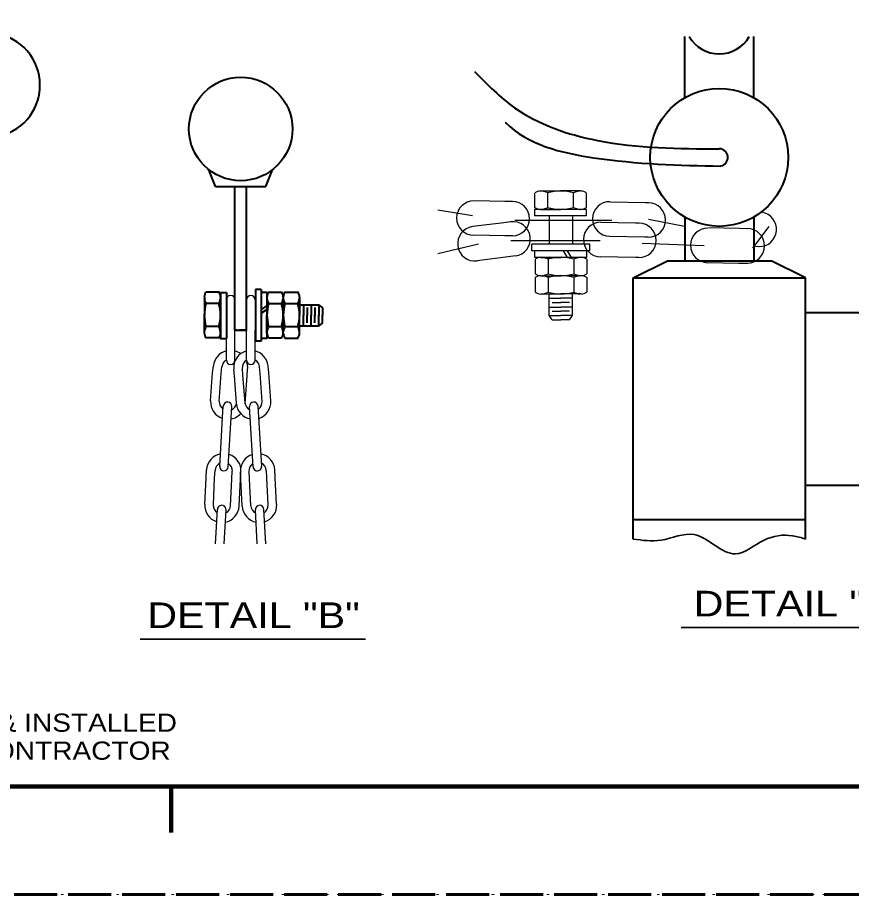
# Model space of a CAD drawing. Extents: x 312583 to 312854, y 144419 to 144597.
# Drawn here: x 312726.34 to 312761.09, y 144418.58 to 144455.15 of the extents above; entities that cross this region are included whole.
import ezdxf
from ezdxf.enums import TextEntityAlignment as Align

# ---------------------------------------------------------------- set-up
doc = ezdxf.new("R2010")
doc.units = 0
doc.header["$LTSCALE"] = 0.3
doc.linetypes.add('DOTTED', pattern=[1.5, 0.3, -1.2])
doc.linetypes.add('LONG_DASHED', pattern=[7.5, 6, -1.5])
for name, color, linetype, lineweight in [('1', 7, 'Continuous', 40), ('62', 7, 'DOTTED', 13), ('63', 7, 'LONG_DASHED', 60)]:
    doc.layers.add(name, color=color, linetype=linetype, lineweight=lineweight)

msp = doc.modelspace()

# ---------------------------------------------------------------- linework, layer by layer
at = {"layer": '1'}
for p, q in [((312754.1462, 144451.8031), (312754.1462, 144454.3561)), ((312757.0212, 144451.8031), (312757.0212, 144454.3561)), ((312734.588, 144448.104), (312734.3197, 144448.8017)), ((312736.6964, 144448.104), (312736.9724, 144448.8017)), ((312734.588, 144448.104), (312736.6964, 144448.104)), ((312735.4007, 144442.1164), (312735.4007, 144448.104)), ((312754.1462, 144446.8274), (312754.1462, 144445.0104)), ((312757.0212, 144446.8274), (312757.0212, 144445.0104)), ((312759.1832, 144444.2898), (312757.7419, 144445.0104)), ((312735.8837, 144442.1164), (312735.8837, 144444.2477)), ((312751.9919, 144444.2898), (312759.1832, 144444.2898)), ((312751.9919, 144434.2234), (312751.9919, 144444.2898)), ((312759.1832, 144434.2234), (312759.1832, 144444.2898)), ((312734.7414, 144443.7034), (312734.197, 144443.7034)), ((312734.8027, 144443.688), (312735.048, 144443.688)), ((312735.048, 144443.688), (312735.048, 144441.7714)), ((312736.497, 144443.8107), (312736.2594, 144443.8107)), ((312736.2594, 144443.8107), (312736.2594, 144441.6564)), ((312736.497, 144443.8107), (312736.497, 144441.6564)), ((312736.7347, 144443.688), (312736.497, 144443.688)), ((312736.7347, 144443.688), (312736.7347, 144441.7714)), ((312736.796, 144443.7034), (312737.348, 144443.7034)), ((312737.4784, 144443.6957), (312738.0304, 144443.6957)), ((312734.128, 144443.4887), (312734.128, 144442.7297)), ((312734.8027, 144443.4887), (312734.8027, 144442.7297)), ((312736.7347, 144443.4887), (312736.7347, 144442.7297)), ((312737.417, 144443.4887), (312737.417, 144442.7297)), ((312737.417, 144443.4887), (312737.417, 144442.7297)), ((312738.0994, 144443.4887), (312738.0994, 144442.7297)), ((312734.7414, 144443.2204), (312734.1894, 144443.2204)), ((312736.497, 144442.9674), (312736.7347, 144443.1207)), ((312736.497, 144442.8217), (312736.7347, 144442.975)), ((312736.8037, 144443.2204), (312737.348, 144443.2204)), ((312737.4784, 144443.2204), (312738.0304, 144443.2204)), ((312738.0994, 144443.1667), (312738.8967, 144443.1667)), ((312738.2527, 144443.1667), (312738.2527, 144442.7297)), ((312738.4137, 144443.0517), (312738.4137, 144442.7297)), ((312738.5747, 144443.1667), (312738.5747, 144442.7297)), ((312738.7357, 144443.0517), (312738.7357, 144442.7297)), ((312739.0577, 144443.0517), (312739.0577, 144442.7297)), ((312734.128, 144441.9937), (312734.128, 144442.7374)), ((312734.8027, 144441.9937), (312734.8027, 144442.7297)), ((312736.7347, 144441.9937), (312736.7347, 144442.7297)), ((312737.417, 144441.9937), (312737.417, 144442.7374)), ((312737.417, 144441.9937), (312737.417, 144442.7297)), ((312738.0994, 144441.9937), (312738.0994, 144442.7374)), ((312738.2527, 144442.3004), (312738.2527, 144442.7374)), ((312738.4137, 144442.4154), (312738.4137, 144442.7374)), ((312738.5747, 144442.3004), (312738.5747, 144442.7374)), ((312738.7357, 144442.4154), (312738.7357, 144442.7374)), ((312739.0577, 144442.4154), (312739.0577, 144442.7374)), ((312734.7414, 144442.2697), (312734.197, 144442.2697)), ((312736.796, 144442.2697), (312737.348, 144442.2697)), ((312737.4784, 144442.2697), (312738.0304, 144442.2697)), ((312738.0994, 144442.3004), (312738.8967, 144442.3004)), ((312735.8837, 144442.1164), (312735.5847, 144442.1164)), ((312734.7414, 144441.7867), (312734.197, 144441.7867)), ((312736.497, 144441.6564), (312736.2594, 144441.6564)), ((312736.7347, 144441.7714), (312736.497, 144441.7714)), ((312736.796, 144441.7867), (312737.348, 144441.7867)), ((312737.4784, 144441.779), (312738.0304, 144441.779)), ((312759.1832, 144435.6571), (312762.0582, 144435.6571)), ((312751.9919, 144434.2234), (312759.1832, 144434.2234)), ((312751.9919, 144433.4031), (312751.9919, 144434.2234)), ((312759.1832, 144433.4031), (312759.1832, 144434.2234))]:
    msp.add_line(p, q, dxfattribs=at)
at = {"layer": '1', "lineweight": 25}
for p, q in [((312747.8979, 144447.2184), (312747.8979, 144447.8318)), ((312748.1355, 144447.9161), (312748.9712, 144447.9161)), ((312748.4422, 144447.2184), (312748.4422, 144447.8318)), ((312749.8145, 144447.9161), (312748.9635, 144447.9161)), ((312749.5155, 144447.2184), (312749.5155, 144447.8394)), ((312750.0522, 144447.2184), (312750.0522, 144447.8318)), ((312743.8575, 144447.1341), (312745.2989, 144446.8964)), ((312748.1355, 144447.1494), (312748.9635, 144447.1494)), ((312749.8222, 144447.1494), (312748.9635, 144447.1494)), ((312750.0445, 144447.1494), (312750.0445, 144446.8811)), ((312747.0622, 144446.6971), (312751.1102, 144446.6971)), ((312750.0445, 144446.8811), (312747.8902, 144446.8811)), ((312749.6842, 144446.8811), (312748.2735, 144446.8811)), ((312748.4959, 144446.8811), (312748.4959, 144445.6928)), ((312749.4695, 144446.8811), (312749.4695, 144445.6928)), ((312752.6359, 144446.7431), (312754.1309, 144446.4518)), ((312756.9829, 144445.5318), (312757.6575, 144446.4364)), ((312746.9012, 144445.8461), (312750.6272, 144445.8461)), ((312745.5519, 144445.7004), (312743.8575, 144445.3018)), ((312747.7675, 144445.4244), (312747.7675, 144445.6928)), ((312750.1979, 144445.6928), (312747.7675, 144445.6928)), ((312750.1979, 144445.4244), (312750.1979, 144445.6928)), ((312752.3675, 144445.7464), (312754.9589, 144445.6391)), ((312757.2282, 144445.5931), (312757.0365, 144445.6084)), ((312750.1979, 144445.4244), (312747.7675, 144445.4244)), ((312747.8979, 144445.1484), (312747.8979, 144445.4244)), ((312750.0599, 144445.1484), (312747.8979, 144445.1484)), ((312748.1509, 144445.1484), (312748.9789, 144445.1484)), ((312749.8299, 144445.1484), (312748.9789, 144445.1484)), ((312749.0862, 144445.4244), (312749.2472, 144445.1484)), ((312749.2472, 144445.4244), (312749.4159, 144445.1484)), ((312750.0599, 144445.1484), (312750.0599, 144445.4244)), ((312747.9132, 144445.0794), (312747.9132, 144444.4661)), ((312748.4575, 144445.0794), (312748.4575, 144444.4661)), ((312749.5309, 144445.0794), (312749.5309, 144444.4584)), ((312750.0675, 144445.0794), (312750.0675, 144444.4661)), ((312748.1432, 144444.3818), (312748.9789, 144444.3818)), ((312748.1509, 144444.3818), (312748.9865, 144444.3818)), ((312749.8299, 144444.3818), (312748.9789, 144444.3818)), ((312749.8299, 144444.3818), (312748.9789, 144444.3818)), ((312747.9132, 144444.3204), (312747.9132, 144443.6994)), ((312748.4575, 144444.3204), (312748.4575, 144443.6994)), ((312749.5309, 144444.3128), (312749.5309, 144443.6918)), ((312750.0675, 144444.3204), (312750.0675, 144443.6994)), ((312735.048, 144443.3737), (312735.048, 144442.1164)), ((312735.4007, 144443.3737), (312735.4007, 144442.1164)), ((312735.8837, 144443.3737), (312735.8837, 144442.1164)), ((312736.244, 144443.3737), (312736.244, 144442.1164)), ((312748.1509, 144443.6228), (312748.9789, 144443.6228)), ((312748.4959, 144442.7258), (312748.4959, 144443.6228)), ((312748.4959, 144443.4464), (312748.9865, 144443.4464)), ((312748.6262, 144443.2624), (312748.9865, 144443.2624)), ((312749.8299, 144443.6228), (312748.9789, 144443.6228)), ((312749.4695, 144443.4464), (312748.9789, 144443.4464)), ((312749.3392, 144443.2624), (312748.9789, 144443.2624)), ((312749.4695, 144442.7258), (312749.4695, 144443.6228)), ((312748.4959, 144443.0784), (312748.9865, 144443.0784)), ((312748.6262, 144442.9021), (312748.9865, 144442.9021)), ((312749.4695, 144443.0784), (312748.9789, 144443.0784)), ((312749.3392, 144442.9021), (312748.9789, 144442.9021)), ((312748.6262, 144442.5418), (312748.9865, 144442.5418)), ((312749.3392, 144442.5418), (312748.9789, 144442.5418)), ((312735.048, 144440.859), (312735.048, 144442.1164)), ((312735.4007, 144440.859), (312735.4007, 144442.1164)), ((312735.8837, 144440.859), (312735.8837, 144442.1164)), ((312736.244, 144440.859), (312736.244, 144442.1164)), ((312734.5957, 144433.2077), (312734.6724, 144434.6414)), ((312734.956, 144433.2077), (312735.0327, 144434.626)), ((312736.3284, 144433.2077), (312736.2594, 144434.626)), ((312736.6887, 144433.2077), (312736.612, 144434.6414))]:
    msp.add_line(p, q, dxfattribs=at)
at = {"layer": '1', "lineweight": 35}
for p, q in [((312754.0035, 144429.7202), (312763.6932, 144429.7202)), ((312731.4584, 144429.2358), (312740.8487, 144429.2358))]:
    msp.add_line(p, q, dxfattribs=at)
at = {"layer": '1', "lineweight": 158}
for p, q in [((312616.5, 144423.0846), (312849, 144423.0846)), ((312732.75, 144421.1646), (312732.75, 144423.0846))]:
    msp.add_line(p, q, dxfattribs=at)
at = {"layer": '1'}
for points in [[(312735.4007, 144442.1164), (312735.8837, 144442.1164), (312735.8837, 144448.104)], [(312751.9919, 144444.2898), (312753.4332, 144445.0104), (312757.7419, 144445.0104)], [(312734.8027, 144443.688), (312734.8027, 144441.7714), (312735.048, 144441.7714)], [(312739.0577, 144443.0517), (312738.8967, 144443.1667), (312738.8967, 144442.7297)], [(312739.0577, 144442.4154), (312738.8967, 144442.3004), (312738.8967, 144442.7374)], [(312759.1832, 144442.8484), (312763.4919, 144442.8484), (312762.0582, 144435.6571)], [(312735.485, 144442.1164), (312735.4007, 144442.1164), (312735.4007, 144442.377)]]:
    msp.add_lwpolyline(points, dxfattribs=at)
at = {"layer": '1', "lineweight": 25}
for points in [[(312746.9702, 144447.4791), (312746.6559, 144447.4791), (312745.3679, 144447.5021)], [(312752.6282, 144447.4178), (312752.4902, 144447.4254), (312751.0412, 144447.4484)], [(312750.0445, 144447.1494), (312747.8902, 144447.1494), (312747.8902, 144446.8811)], [(312746.8859, 144446.6281), (312746.6022, 144446.5898), (312745.3142, 144446.4364)], [(312752.2372, 144446.5744), (312752.0992, 144446.5744), (312750.6502, 144446.6051)], [(312756.7682, 144446.3444), (312756.4232, 144446.3521), (312755.1352, 144446.3751)], [(312746.9625, 144446.0454), (312746.6482, 144446.0454), (312745.3372, 144446.0684)], [(312752.6282, 144445.9918), (312752.4825, 144445.9918), (312751.0182, 144446.0224)], [(312747.1005, 144445.2098), (312746.7862, 144445.1638), (312745.4905, 144445.0104)], [(312752.2372, 144445.1408), (312752.0915, 144445.1408), (312750.6195, 144445.1638)], [(312756.7759, 144444.8878), (312756.3925, 144444.8878), (312755.0815, 144444.9184)], [(312748.6185, 144442.5418), (312748.4959, 144442.7258), (312748.9865, 144442.7258)], [(312749.3392, 144442.5418), (312749.4695, 144442.7258), (312748.9789, 144442.7258)], [(312734.3887, 144439.1647), (312734.473, 144440.33), (312734.5037, 144440.6214)], [(312734.749, 144439.1417), (312734.8334, 144440.2994), (312734.8564, 144440.583)], [(312735.462, 144439.065), (312735.3777, 144440.2074), (312735.3547, 144440.4757)], [(312735.8224, 144439.088), (312735.738, 144440.238), (312735.715, 144440.514)], [(312735.8224, 144439.0497), (312735.9067, 144440.2074), (312735.9297, 144440.4757)], [(312736.5354, 144439.1417), (312736.4587, 144440.2994), (312736.428, 144440.583)], [(312736.8957, 144439.1647), (312736.8114, 144440.33), (312736.7807, 144440.6214)], [(312734.772, 144436.4354), (312734.9024, 144438.72), (312734.9177, 144438.95)], [(312735.1247, 144436.42), (312735.255, 144438.697), (312735.2704, 144438.927)], [(312736.1597, 144436.42), (312736.0294, 144438.697), (312736.014, 144438.927)], [(312736.52, 144436.4354), (312736.3897, 144438.72), (312736.3744, 144438.95)], [(312734.1434, 144434.8484), (312734.2047, 144435.9754), (312734.22, 144436.2897)], [(312734.5037, 144434.833), (312734.5574, 144435.9524), (312734.5804, 144436.2667)], [(312735.2167, 144434.7947), (312735.278, 144435.914), (312735.2934, 144436.2284)], [(312735.577, 144434.7717), (312735.6384, 144435.8987), (312735.6537, 144436.2054)], [(312735.7074, 144434.7717), (312735.646, 144435.8987), (312735.6307, 144436.2054)], [(312736.0677, 144434.7947), (312736.0064, 144435.914), (312735.991, 144436.2284)], [(312736.7884, 144434.833), (312736.727, 144435.9524), (312736.7117, 144436.2667)], [(312737.141, 144434.8484), (312737.0797, 144435.9754), (312737.0644, 144436.2897)]]:
    msp.add_lwpolyline(points, dxfattribs=at)
at = {"layer": '1'}
for centre, radius in [((312735.6422, 144450.5018), 2.1562), ((312755.585, 144449.3172), 2.875)]:
    msp.add_circle(centre, radius, dxfattribs=at)
for centre, radius, start, end in [((312725.1006, 144452.3297), 2.1777, 278.04577, 81.95422), ((312755.585, 144455.0672), 1.4375, 209.73571, 330.26429), ((312755.585, 144449.3172), 0.3594, 280.70135, 90), ((312734.5181, 144443.4778), 0.3946, 145.8703, 178.33743), ((312734.4094, 144443.4778), 0.3946, 1.66257, 34.1297), ((312737.13, 144443.4778), 0.3946, 145.8703, 178.33743), ((312737.0212, 144443.4778), 0.3946, 1.66257, 34.1297), ((312737.8104, 144443.4759), 0.3946, 145.8703, 178.33743), ((312737.7016, 144443.4759), 0.3946, 1.66257, 34.1297), ((312735.2288, 144443.6684), 1.13, 191.77014, 203.36365), ((312733.6986, 144443.6684), 1.13, 336.63635, 348.22986), ((312737.8407, 144443.6684), 1.13, 191.77014, 203.36365), ((312736.3105, 144443.6684), 1.13, 336.63635, 348.22986), ((312738.5211, 144443.6665), 1.13, 191.77014, 203.36365), ((312736.9909, 144443.6665), 1.13, 336.63635, 348.22986), ((312736.1613, 144442.6923), 2.0394, 164.99798, 178.595), ((312732.7661, 144442.6923), 2.0394, 1.405, 15.00202), ((312738.7732, 144442.6923), 2.0394, 164.99798, 178.595), ((312735.378, 144442.6923), 2.0394, 1.405, 15.00202), ((312739.4536, 144442.6904), 2.0394, 164.99798, 178.595), ((312736.0584, 144442.6904), 2.0394, 1.405, 15.00202), ((312736.1613, 144442.7924), 2.0394, 181.405, 195.00202), ((312732.7661, 144442.7924), 2.0394, 344.99798, 358.595), ((312738.7732, 144442.7924), 2.0394, 181.405, 195.00202), ((312735.378, 144442.7924), 2.0394, 344.99798, 358.595), ((312739.4536, 144442.7904), 2.0394, 181.405, 195.00202), ((312736.0584, 144442.7904), 2.0394, 344.99798, 358.595), ((312735.2288, 144441.8163), 1.13, 156.63635, 168.22986), ((312733.6986, 144441.8163), 1.13, 11.77014, 23.36365), ((312737.8407, 144441.8163), 1.13, 156.63635, 168.22986), ((312736.3105, 144441.8163), 1.13, 11.77014, 23.36365), ((312738.5211, 144441.8144), 1.13, 156.63635, 168.22986), ((312736.9909, 144441.8144), 1.13, 11.77014, 23.36365), ((312734.5181, 144442.0069), 0.3946, 181.66257, 214.1297), ((312734.4094, 144442.0069), 0.3946, 325.8703, 358.33743), ((312737.13, 144442.0069), 0.3946, 181.66257, 214.1297), ((312737.0212, 144442.0069), 0.3946, 325.8703, 358.33743), ((312737.8104, 144442.005), 0.3946, 181.66257, 214.1297), ((312737.7016, 144442.005), 0.3946, 325.8703, 358.33743)]:
    msp.add_arc(centre, radius, start, end, dxfattribs=at)
at = {"layer": '1', "lineweight": 25}
for centre, radius, start, end in [((312748.1485, 144447.4703), 0.444, 91.66257, 124.1297), ((312747.9341, 144446.6708), 1.2713, 66.63635, 78.22986), ((312749.0322, 144445.6217), 2.2943, 91.405, 105.00202), ((312748.9197, 144445.6217), 2.2943, 74.99798, 88.595), ((312750.0177, 144446.6708), 1.2713, 101.77014, 113.36365), ((312749.8033, 144447.4703), 0.444, 55.8703, 88.33743), ((312745.357, 144446.7864), 0.7188, 89.37363, 269.37362), ((312746.961, 144446.7641), 0.7188, 269.61189, 89.61189), ((312751.0236, 144446.7519), 0.7188, 89.37363, 269.37362), ((312752.6276, 144446.7066), 0.7188, 269.61189, 89.61189), ((312748.1485, 144447.5927), 0.444, 235.8703, 268.33743), ((312747.9341, 144448.3922), 1.2713, 281.77014, 293.36365), ((312749.0322, 144449.4413), 2.2943, 254.99798, 268.595), ((312748.9197, 144449.4413), 2.2943, 271.405, 285.00202), ((312750.0177, 144448.3922), 1.2713, 246.63635, 258.22986), ((312749.8033, 144447.5927), 0.444, 271.66257, 304.1297), ((312757.2506, 144446.3156), 0.7188, 269.61189, 80.66149), ((312746.9925, 144445.9181), 0.7188, 277.61189, 97.61189), ((312750.6441, 144445.8923), 0.7188, 89.37363, 269.37362), ((312752.2366, 144445.8585), 0.7188, 269.61189, 89.61189), ((312745.4022, 144445.7171), 0.7188, 97.37363, 277.37362), ((312755.1032, 144445.645), 0.7188, 89.37363, 269.37362), ((312756.7561, 144445.6285), 0.7188, 269.61189, 89.61189), ((312748.1636, 144444.7066), 0.444, 91.66257, 124.1297), ((312747.9492, 144443.9071), 1.2713, 66.63635, 78.22986), ((312749.0473, 144442.858), 2.2943, 91.405, 105.00202), ((312748.9348, 144442.858), 2.2943, 74.99798, 88.595), ((312750.0328, 144443.9071), 1.2713, 101.77014, 113.36365), ((312749.8184, 144444.7066), 0.444, 55.8703, 88.33743), ((312748.1615, 144443.9412), 0.444, 91.66257, 124.1297), ((312748.1636, 144444.829), 0.444, 235.8703, 268.33743), ((312747.9471, 144443.1416), 1.2713, 66.63635, 78.22986), ((312747.9492, 144445.6285), 1.2713, 281.77014, 293.36365), ((312749.0451, 144442.0926), 2.2943, 91.405, 105.00202), ((312749.0473, 144446.6776), 2.2943, 254.99798, 268.595), ((312748.9326, 144442.0926), 2.2943, 74.99798, 88.595), ((312748.9348, 144446.6776), 2.2943, 271.405, 285.00202), ((312750.0307, 144443.1416), 1.2713, 101.77014, 113.36365), ((312750.0328, 144445.6285), 1.2713, 246.63635, 258.22986), ((312749.8163, 144443.9412), 0.444, 55.8703, 88.33743), ((312749.8184, 144444.829), 0.444, 271.66257, 304.1297), ((312748.1615, 144444.0635), 0.444, 235.8703, 268.33743), ((312747.9471, 144444.8631), 1.2713, 281.77014, 293.36365), ((312749.0451, 144445.9121), 2.2943, 254.99798, 268.595), ((312748.9326, 144445.9121), 2.2943, 271.405, 285.00202), ((312750.0307, 144444.8631), 1.2713, 246.63635, 258.22986), ((312749.8163, 144444.0635), 0.444, 271.66257, 304.1297), ((312735.2244, 144443.3737), 0.1792, 0, 180), ((312736.06, 144443.3737), 0.1792, 0, 180), ((312735.2173, 144440.5509), 0.7188, 103.93517, 174.22394), ((312736.0671, 144440.5509), 0.7188, 104.9421, 185.70589), ((312735.2173, 144440.5509), 0.7188, 53.75949, 75.07528), ((312736.0671, 144440.5509), 0.7188, 5.77606, 76.06483), ((312735.2173, 144440.5509), 0.3594, 118.79308, 174.24956), ((312735.2244, 144440.859), 0.1792, 180, 0), ((312736.0671, 144440.5509), 0.3594, 121.04328, 185.88348), ((312735.2173, 144440.5509), 0.7188, 352.15115, 24.72299), ((312736.06, 144440.859), 0.1792, 180, 0), ((312736.0671, 144440.5509), 0.3594, 5.75044, 61.20692), ((312735.1077, 144439.1178), 0.7188, 175.96906, 251.45209), ((312735.1077, 144439.1178), 0.3594, 175.96906, 235.88081), ((312735.095, 144438.938), 0.1792, 355.96906, 175.96906), ((312735.1077, 144439.1178), 0.3594, 295.64054, 349.45786), ((312736.1767, 144439.1178), 0.7188, 184.03094, 259.67174), ((312736.1767, 144439.1178), 0.3594, 184.03094, 244.29523), ((312736.1894, 144438.938), 0.1792, 4.03094, 184.03094), ((312736.1767, 144439.1178), 0.3594, 304.11919, 4.03094), ((312736.1767, 144439.1178), 0.7188, 288.54791, 4.03094), ((312735.1077, 144439.1178), 0.7188, 280.28682, 318.04616), ((312734.9373, 144436.2479), 0.7188, 101.22581, 176.70885), ((312734.9373, 144436.2479), 0.7188, 356.70885, 72.34965), ((312736.3471, 144436.2479), 0.7188, 107.65035, 183.29115), ((312736.3471, 144436.2479), 0.7188, 3.29115, 78.77419), ((312734.9373, 144436.2479), 0.3594, 116.7971, 176.70885), ((312734.9477, 144436.4277), 0.1792, 176.70885, 356.70885), ((312734.9373, 144436.2479), 0.3594, 356.70885, 56.97314), ((312736.3471, 144436.2479), 0.3594, 123.02686, 183.29115), ((312736.3367, 144436.4277), 0.1792, 183.29115, 3.29115), ((312736.3471, 144436.2479), 0.3594, 3.29115, 63.2029), ((312734.8604, 144434.8124), 0.7188, 176.99734, 252.48037), ((312736.424, 144434.8124), 0.7188, 287.51963, 3.00266), ((312734.8604, 144434.8124), 0.3594, 176.99734, 236.90909), ((312734.851, 144434.6325), 0.1792, 356.99734, 176.99734), ((312734.8604, 144434.8124), 0.7188, 281.35653, 356.99734), ((312734.8604, 144434.8124), 0.3594, 296.73305, 356.99734), ((312736.424, 144434.8124), 0.7188, 183.00266, 258.64347), ((312736.424, 144434.8124), 0.3594, 183.00266, 243.26695), ((312736.4334, 144434.6325), 0.1792, 3.00266, 183.00266), ((312736.424, 144434.8124), 0.3594, 303.09091, 3.00266)]:
    msp.add_arc(centre, radius, start, end, dxfattribs=at)
at = {"layer": '1'}
for points in [[(312745.3909, 144452.8918), (312747.0545, 144451.3891), (312750.5045, 144450.0244), (312755.5875, 144449.6718)], [(312746.6635, 144450.7758), (312746.6712, 144450.7681), (312750.3435, 144449.3038), (312755.6565, 144448.9511)]]:
    msp.add_spline(points, degree=3, dxfattribs=at)
at = {"layer": '1', "lineweight": 35}
msp.add_spline([(312751.9919, 144433.4031), (312753.1572, 144433.3571), (312754.5372, 144433.5871), (312756.2545, 144432.7821), (312757.4505, 144433.3571), (312758.6389, 144433.5411), (312759.1832, 144433.4031)], degree=3, dxfattribs=at)
at = {"layer": '62'}
msp.add_lwpolyline([(312601.2, 144418.5846), (312853.5, 144418.5846), (312853.5, 144596.7846)], dxfattribs=at)
at = {"layer": '63'}
msp.add_line((312851.75, 144418.5846), (312583.526, 144418.5846), dxfattribs=at)

# ---------------------------------------------------------------- texts
at = {"layer": '1', "width": 1.2}
for s, p in [('DETAIL "C"', (312758.9924, 144430.1771)), ('DETAIL "B"', (312736.1767, 144429.6913))]:
    msp.add_text(s, height=1.07, dxfattribs=at).set_placement(p, align=Align.CENTER)
at = {"layer": '1', "width": 1.15}
for s, p in [('SAFETY CHAIN REQUIRED TO BE FURNISHED & INSTALLED', (312699.2156, 144425.3677)), ('ON ALL CONTRACT INSTALLATIONS BY THE CONTRACTOR', (312699.2156, 144424.2014))]:
    msp.add_text(s, height=0.76, dxfattribs=at).set_placement(p)

doc.saveas('drawing.dxf')
